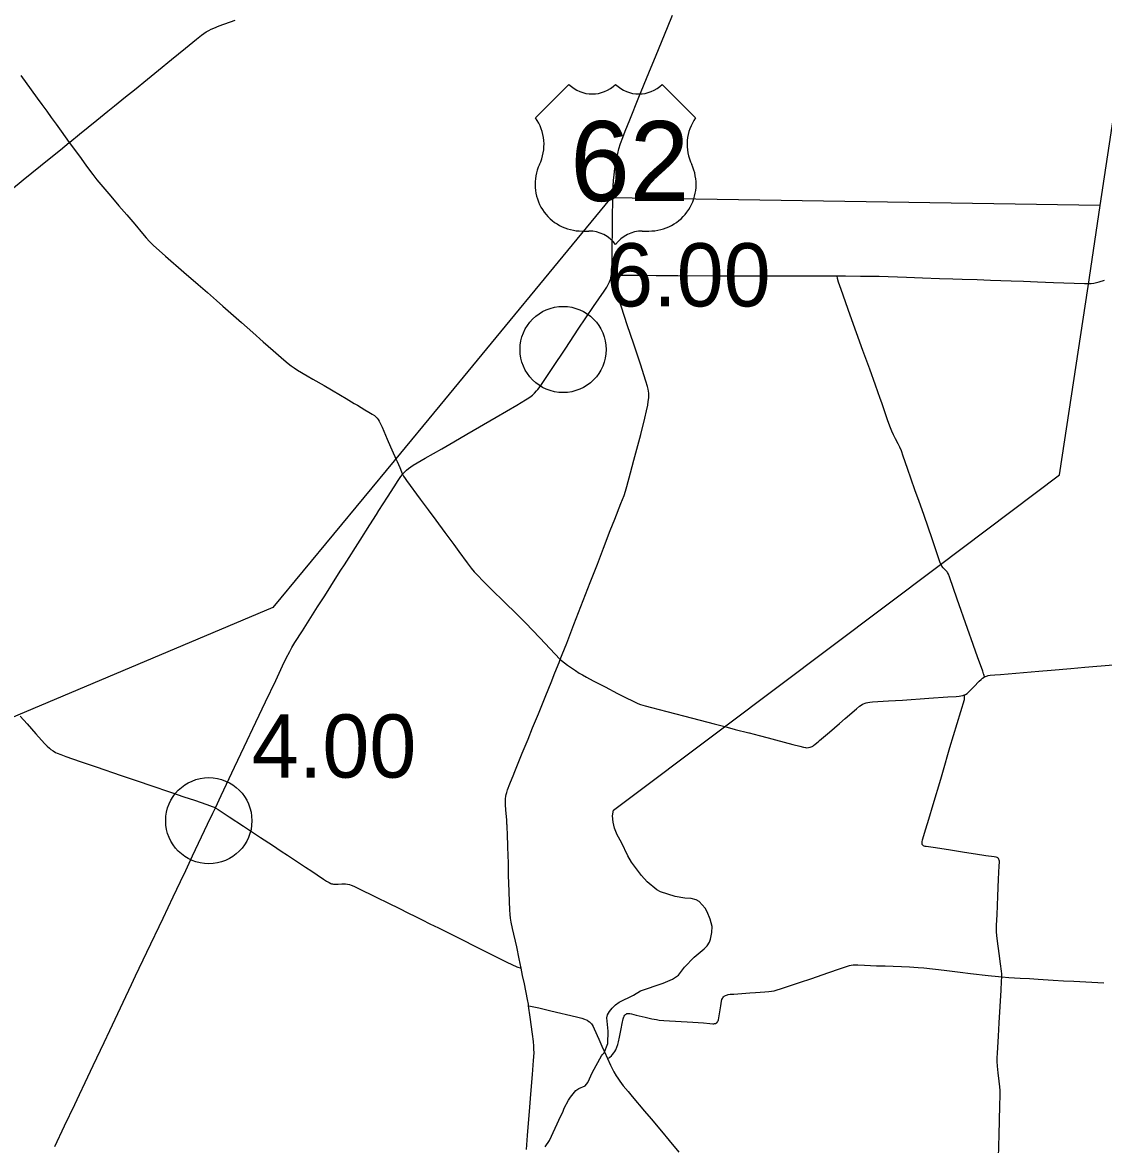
# Model space of a CAD drawing. Extents: x 1597222 to 1925846, y 496284 to 911751.
# Drawn here: x 1678855 to 1697673, y 517019 to 536551 of the extents above; entities that cross this region are included whole.
import ezdxf

# ---------------------------------------------------------------- set-up
doc = ezdxf.new("R2010")
doc.units = 0
for name, color, linetype in [('Default', 7, 'Continuous'), ('GM_X_County_Road', 7, 'Continuous'), ('GM_X_Township', 7, 'Continuous'), ('GM_X_Township_Road', 7, 'Continuous'), ('GM_X_US_Route', 7, 'Continuous'), ('GM_X_US_Shield', 7, 'Continuous')]:
    doc.layers.add(name, color=color, linetype=linetype)

msp = doc.modelspace()

# ---------------------------------------------------------------- linework, layer by layer
at = {"layer": 'Default'}
for centre in [(1688266, 530858), (1688266, 530858), (1682099, 522656), (1682099, 522656)]:
    msp.add_circle(centre, 750, dxfattribs=at)
at = {"layer": 'GM_X_County_Road'}
for points in [[(1679671, 534461), (1679681, 534469), (1679846, 534605), (1680152, 534852), (1680343, 535007), (1680458, 535099), (1680649, 535254), (1680803, 535378), (1681032, 535564), (1681222, 535719), (1681452, 535905), (1681693, 536102), (1681884, 536258), (1681973, 536330), (1682013, 536359), (1682054, 536387), (1682097, 536412), (1682141, 536434), (1682186, 536453), (1682278, 536489), (1682556, 536588)], [(1678825, 535628), (1679008, 535376), (1679114, 535230), (1679192, 535124), (1679279, 535005), (1679356, 534899), (1679442, 534779), (1679528, 534659), (1679671, 534461)], [(1678662, 533644), (1678866, 533809), (1679171, 534057), (1679376, 534222), (1679516, 534335), (1679671, 534461)], [(1679671, 534461), (1679691, 534432), (1679875, 534181), (1679973, 534049), (1680081, 533905), (1680152, 533814), (1680255, 533687), (1680393, 533524), (1680531, 533361), (1680670, 533200), (1680809, 533038), (1680946, 532875), (1681011, 532800), (1681067, 532740), (1681137, 532671), (1681234, 532582), (1681345, 532484), (1681667, 532204), (1681915, 531990), (1682076, 531850), (1682235, 531708), (1682346, 531611), (1682666, 531329), (1682863, 531156), (1683047, 530993), (1683219, 530840), (1683403, 530677), (1683479, 530614), (1683531, 530574), (1683585, 530536), (1683641, 530501), (1683811, 530402), (1683911, 530344), (1684109, 530229), (1684236, 530154), (1684391, 530062), (1684490, 530003), (1684631, 529920), (1684688, 529887), (1684814, 529810), (1684885, 529769), (1684941, 529735), (1684981, 529707), (1685005, 529687), (1685027, 529663), (1685046, 529637), (1685064, 529610), (1685087, 529566), (1685114, 529507), (1685205, 529297), (1685264, 529161), (1685311, 529057), (1685339, 528997), (1685357, 528956)], [(1688217, 525463), (1688251, 525549), (1688329, 525748), (1688453, 526069), (1688738, 526803), (1688864, 527124), (1688969, 527399), (1689088, 527705), (1689165, 527904), (1689273, 528179), (1689327, 528317), (1689354, 528394), (1689377, 528473), (1689441, 528711), (1689500, 528933), (1689618, 529376), (1689690, 529663), (1689720, 529791), (1689739, 529888), (1689749, 529953), (1689756, 530018), (1689760, 530053), (1689760, 530099), (1689755, 530134), (1689749, 530166), (1689737, 530214), (1689708, 530309), (1689611, 530605), (1689497, 530948), (1689384, 531290), (1689229, 531757), (1689137, 532026), (1689125, 532055), (1689106, 532081), (1689095, 532098)], [(1689107, 532152), (1689163, 532151), (1689393, 532150), (1689622, 532149), (1689885, 532147), (1690262, 532146), (1690885, 532143), (1691163, 532141), (1691426, 532140), (1691885, 532140), (1692409, 532139), (1693039, 532138)], [(1693039, 532138), (1693180, 532138), (1693442, 532136), (1693639, 532135), (1693770, 532133), (1694246, 532118), (1694524, 532107), (1694819, 532096), (1695048, 532090), (1695212, 532085), (1695474, 532075), (1695704, 532067), (1696064, 532053), (1696277, 532045), (1696523, 532035), (1696801, 532024), (1697162, 532010), (1697342, 532004), (1697407, 532004), (1697414, 532004)], [(1697414, 532004), (1697456, 532006), (1697505, 532012), (1697552, 532022), (1697599, 532035), (1697692, 532067)], [(1685357, 528956), (1685379, 528908), (1685425, 528802), (1685453, 528730), (1685466, 528698), (1685472, 528686)], [(1685472, 528686), (1685476, 528676), (1685490, 528652), (1685515, 528611), (1685542, 528575), (1685778, 528254), (1685915, 528070), (1686052, 527885), (1686207, 527673), (1686363, 527462), (1686450, 527343), (1686596, 527145), (1686666, 527053), (1686718, 526990), (1686763, 526942), (1686889, 526812), (1687005, 526697), (1687264, 526445), (1687439, 526273), (1687613, 526098), (1687863, 525838), (1688217, 525463)], [(1687415, 523482), (1687556, 523831), (1687656, 524074), (1687736, 524271), (1687835, 524514), (1687964, 524834), (1688056, 525062), (1688123, 525229), (1688196, 525412), (1688217, 525463)], [(1688217, 525463), (1688238, 525442), (1688345, 525366), (1688479, 525271), (1688548, 525226), (1688604, 525193), (1688676, 525153), (1688792, 525092), (1688997, 524989), (1689215, 524873), (1689331, 524813), (1689507, 524725), (1689567, 524698), (1689614, 524681), (1689692, 524655), (1689802, 524624), (1690072, 524554), (1690517, 524440), (1690898, 524340), (1691057, 524300), (1691082, 524293)], [(1695601, 525158), (1695621, 525168), (1695651, 525179), (1695667, 525182), (1695699, 525187), (1695781, 525195), (1695879, 525203), (1696549, 525260), (1696761, 525277), (1697104, 525307), (1697349, 525328), (1697839, 525371)], [(1695253, 524847), (1695269, 524854), (1695297, 524872), (1695322, 524893), (1695347, 524916), (1695415, 524987), (1695506, 525082), (1695541, 525116), (1695566, 525136), (1695593, 525154), (1695601, 525158)], [(1691506, 524183), (1691676, 524139), (1691834, 524098), (1691961, 524066), (1692262, 523985), (1692389, 523951), (1692453, 523934), (1692486, 523928), (1692502, 523927), (1692536, 523928), (1692568, 523935), (1692584, 523941), (1692599, 523948), (1692613, 523956), (1692627, 523966), (1692654, 523986), (1692704, 524029), (1692729, 524050), (1692904, 524199), (1693077, 524350), (1693176, 524436), (1693375, 524606), (1693426, 524648), (1693452, 524667), (1693480, 524684), (1693494, 524691), (1693524, 524703), (1693539, 524707), (1693571, 524715), (1693603, 524720), (1693652, 524724), (1693930, 524740), (1694175, 524756), (1694633, 524789), (1694961, 524811), (1695108, 524820), (1695157, 524824), (1695190, 524828), (1695222, 524836), (1695238, 524841), (1695253, 524847)], [(1678816, 524474), (1678936, 524340), (1679090, 524170), (1679242, 523998), (1679288, 523951), (1679324, 523918), (1679349, 523897), (1679389, 523870), (1679431, 523845), (1679461, 523831), (1679521, 523806), (1679613, 523772), (1679861, 523687), (1680141, 523593), (1680576, 523444), (1680871, 523344), (1681089, 523270), (1681430, 523155), (1681663, 523074), (1681849, 523012), (1682066, 522937), (1682159, 522903), (1682190, 522891), (1682213, 522880)], [(1691082, 524293), (1691263, 524245), (1691501, 524184), (1691506, 524183)], [(1687303, 522248), (1687298, 522381), (1687297, 522413), (1687293, 522544), (1687291, 522577), (1687289, 522593), (1687288, 522609), (1687284, 522674), (1687270, 522838), (1687263, 522936), (1687262, 522985), (1687265, 523034), (1687270, 523082), (1687276, 523114), (1687284, 523145), (1687300, 523192), (1687341, 523299), (1687408, 523466), (1687415, 523482)], [(1682213, 522880), (1682220, 522877), (1682262, 522851), (1682454, 522725), (1682701, 522562), (1683001, 522363), (1683207, 522228), (1683357, 522128), (1683467, 522056), (1683659, 521930), (1683782, 521849), (1683892, 521776), (1683987, 521712), (1684095, 521639), (1684150, 521602), (1684192, 521578), (1684221, 521564), (1684237, 521559), (1684252, 521556), (1684268, 521553), (1684300, 521551), (1684349, 521553), (1684415, 521557), (1684448, 521557), (1684481, 521556), (1684514, 521552), (1684546, 521544), (1684578, 521534), (1684624, 521516), (1684684, 521489), (1685022, 521322), (1685213, 521228), (1685419, 521126), (1685566, 521052), (1685698, 520987), (1685815, 520928), (1685948, 520863), (1686095, 520790), (1686388, 520644), (1686550, 520563), (1686697, 520490), (1687122, 520277), (1687284, 520196), (1687462, 520113), (1687535, 520089)], [(1687535, 520089), (1687502, 520252), (1687458, 520460), (1687385, 520780), (1687361, 520892), (1687349, 520957), (1687342, 521021), (1687336, 521103), (1687331, 521250), (1687321, 521578), (1687317, 521692), (1687317, 521791), (1687315, 521922), (1687311, 522053), (1687304, 522200), (1687303, 522248)], [(1689039, 518514), (1689067, 518528), (1689082, 518540), (1689106, 518562), (1689128, 518587), (1689148, 518613), (1689165, 518640), (1689181, 518669), (1689201, 518714), (1689218, 518760), (1689231, 518808), (1689249, 518888), (1689276, 519033), (1689296, 519129), (1689314, 519209), (1689324, 519241), (1689331, 519256), (1689340, 519269), (1689351, 519281), (1689364, 519291), (1689378, 519298), (1689394, 519302), (1689410, 519303), (1689427, 519301), (1689459, 519294), (1689538, 519274), (1689697, 519235), (1689809, 519210), (1689890, 519194), (1689938, 519187), (1690020, 519179), (1690527, 519149), (1690707, 519136), (1690822, 519126), (1690872, 519123), (1690888, 519123), (1690904, 519125), (1690920, 519129), (1690934, 519137), (1690946, 519146), (1690956, 519159), (1690963, 519174), (1690968, 519189), (1690975, 519222), (1691009, 519433), (1691023, 519514), (1691031, 519546), (1691038, 519561), (1691045, 519575), (1691055, 519588), (1691067, 519599), (1691080, 519609), (1691094, 519616), (1691110, 519622), (1691125, 519626), (1691142, 519630), (1691174, 519634), (1691240, 519639), (1691518, 519658), (1691616, 519666), (1691780, 519676), (1691845, 519681), (1691894, 519687), (1691942, 519697), (1691990, 519710), (1692052, 519729), (1692207, 519782), (1692378, 519839), (1692596, 519912), (1692876, 520007), (1693093, 520083), (1693201, 520120), (1693249, 520134), (1693281, 520141), (1693313, 520145), (1693346, 520147), (1693395, 520147), (1693510, 520142), (1693723, 520132), (1693870, 520127), (1694296, 520110), (1694444, 520102), (1694542, 520094), (1694901, 520055), (1695177, 520020), (1695357, 519999), (1695666, 519962), (1695846, 519943), (1695902, 519939)], [(1687664, 519436), (1687661, 519464), (1687647, 519545), (1687593, 519818), (1687562, 519963), (1687535, 520089)], [(1695902, 519939), (1696025, 519929), (1696222, 519917), (1696386, 519907), (1696533, 519898), (1696795, 519881), (1696975, 519871), (1697155, 519861), (1697679, 519836)], [(1687627, 516931), (1687647, 517176), (1687686, 517667), (1687703, 517896), (1687733, 518241), (1687753, 518480), (1687760, 518616), (1687759, 518681), (1687758, 518733), (1687751, 518812), (1687731, 518943), (1687690, 519236), (1687664, 519436)], [(1687664, 519436), (1687698, 519429), (1687842, 519396), (1688050, 519347), (1688497, 519243), (1688592, 519219), (1688640, 519204), (1688670, 519191), (1688685, 519184), (1688699, 519175), (1688726, 519154), (1688738, 519143), (1688749, 519131), (1688760, 519118), (1688770, 519104), (1688787, 519076), (1688808, 519031), (1688889, 518852), (1688942, 518732), (1688987, 518631)], [(1688987, 518631), (1689039, 518514)], [(1689039, 518514), (1689090, 518403), (1689126, 518329), (1689149, 518286), (1689190, 518216), (1689217, 518175), (1689254, 518121), (1689314, 518044), (1689396, 517942), (1689470, 517854), (1689682, 517603), (1689798, 517465), (1689976, 517251), (1690113, 517088), (1690281, 516886)]]:
    msp.add_lwpolyline(points, dxfattribs=at)
at = {"layer": 'GM_X_Township'}
for points in [[(1687952, 516977), (1688030, 517088), (1688224, 517518), (1688259, 517580), (1688284, 517652), (1688361, 517791), (1688394, 517843), (1688490, 517960), (1688540, 517993), (1688651, 518042), (1688698, 518100), (1688778, 518279), (1688934, 518563), (1688947, 518578), (1688979, 518615), (1689047, 518780), (1689048, 518991), (1689027, 519224), (1689041, 519279), (1689074, 519337), (1689119, 519393), (1689180, 519452), (1689242, 519497), (1689494, 519622), (1689616, 519693), (1690006, 519830), (1690169, 519896), (1690272, 519969), (1690380, 520106), (1690549, 520280), (1690719, 520425), (1690774, 520480), (1690812, 520542), (1690831, 520596), (1690853, 520709), (1690858, 520816), (1690825, 520942), (1690771, 521071), (1690736, 521132), (1690635, 521247), (1690583, 521280), (1690497, 521301), (1690387, 521308), (1690215, 521337), (1689960, 521418), (1689896, 521451), (1689729, 521593), (1689632, 521701), (1689459, 521933), (1689392, 522044), (1689281, 522278), (1689208, 522409), (1689162, 522526), (1689137, 522633), (1689124, 522743), (1689142, 522837), (1691050, 524271), (1694788, 527081), (1696909, 528675), (1697404, 531952), (1697617, 533364), (1698092, 536511)], [(1697617, 533364), (1689097, 533498), (1689075, 533471), (1686122, 529882), (1685324, 528919), (1683211, 526366), (1678773, 524491), (1673121, 522104), (1670207, 520873), (1664451, 518441), (1661353, 517132), (1661136, 517041)]]:
    msp.add_lwpolyline(points, dxfattribs=at)
at = {"layer": 'GM_X_Township_Road'}
for points in [[(1694842, 527119), (1694832, 527143), (1694779, 527299), (1694686, 527579), (1694626, 527750), (1694545, 527984), (1694461, 528213), (1694391, 528414), (1694262, 528786), (1694188, 529003), (1694154, 529096), (1694129, 529156), (1694101, 529216), (1694054, 529302), (1694016, 529375), (1693989, 529434), (1693952, 529526), (1693912, 529633), (1693870, 529758), (1693813, 529929), (1693786, 530006), (1693704, 530238), (1693603, 530515), (1693486, 530840), (1693265, 531457), (1693104, 531905), (1693062, 532029), (1693044, 532094), (1693039, 532138)], [(1695409, 525707), (1695403, 525723), (1695304, 526001), (1695124, 526512), (1694989, 526899), (1694972, 526945), (1694958, 526975), (1694949, 526988), (1694939, 527001), (1694928, 527014), (1694881, 527059), (1694860, 527084), (1694844, 527113), (1694842, 527119)], [(1695601, 525158), (1695589, 525198), (1695584, 525213), (1695569, 525260), (1695480, 525507), (1695409, 525707)], [(1695902, 519939), (1695903, 519955), (1695901, 519988), (1695897, 520037), (1695880, 520167), (1695856, 520346), (1695827, 520558), (1695815, 520655), (1695811, 520721), (1695810, 520770), (1695811, 520836), (1695819, 521016), (1695834, 521344), (1695845, 521639), (1695857, 521869), (1695860, 521935), (1695860, 521951), (1695857, 521967), (1695853, 521983), (1695845, 521997), (1695833, 522008), (1695819, 522016), (1695803, 522021), (1695771, 522027), (1695624, 522047), (1695446, 522075), (1695251, 522105), (1695008, 522142), (1694748, 522182), (1694586, 522206), (1694569, 522209), (1694553, 522214), (1694539, 522221), (1694527, 522231), (1694518, 522244), (1694513, 522259), (1694513, 522275), (1694514, 522291), (1694522, 522324), (1694580, 522512), (1694631, 522685), (1694706, 522937), (1694839, 523377), (1694876, 523503), (1695000, 523928), (1695252, 524765), (1695255, 524790), (1695254, 524823), (1695253, 524847)], [(1695842, 516793), (1695856, 517187), (1695869, 517695), (1695873, 517876), (1695872, 517958), (1695868, 518023), (1695857, 518121), (1695839, 518268), (1695829, 518382), (1695824, 518464), (1695824, 518530), (1695826, 518612), (1695844, 518907), (1695856, 519136), (1695891, 519709), (1695899, 519857), (1695902, 519939)]]:
    msp.add_lwpolyline(points, dxfattribs=at)
at = {"layer": 'GM_X_US_Route'}
msp.add_lwpolyline([(1679422, 516988), (1679590, 517344), (1679765, 517715), (1679849, 517893), (1679948, 518101), (1680088, 518397), (1680278, 518798), (1680375, 519006), (1680608, 519495), (1680755, 519806), (1680825, 519955), (1681022, 520370), (1681304, 520962), (1681481, 521332), (1681607, 521599), (1681698, 521792), (1681817, 522044), (1682077, 522593), (1682168, 522785), (1682213, 522880), (1682316, 523097), (1682456, 523393), (1682548, 523586), (1682717, 523942), (1682920, 524372), (1683088, 524728), (1683265, 525098), (1683383, 525350), (1683447, 525483), (1683507, 525600), (1683547, 525672), (1683598, 525756), (1683729, 525963), (1683993, 526379), (1684116, 526573), (1684327, 526905), (1684399, 527015), (1684462, 527111), (1684734, 527541), (1684902, 527804), (1685016, 527984), (1685060, 528053), (1685209, 528288), (1685323, 528469), (1685394, 528579), (1685441, 528646), (1685471, 528685), (1685472, 528686), (1685503, 528721), (1685538, 528755), (1685576, 528786), (1685616, 528815), (1685656, 528842), (1685726, 528885), (1685868, 528966), (1686153, 529130), (1686366, 529253), (1686593, 529385), (1687103, 529682), (1687458, 529888), (1687614, 529980), (1687669, 530015), (1687709, 530045), (1687735, 530065), (1687771, 530099), (1687804, 530136), (1687825, 530161), (1687864, 530214), (1688074, 530528), (1688312, 530882), (1688531, 531209), (1688796, 531605), (1688980, 531876), (1689025, 531945), (1689049, 531988), (1689071, 532033), (1689089, 532079), (1689095, 532098), (1689099, 532111), (1689106, 532143), (1689107, 532152), (1689110, 532176), (1689114, 532225), (1689118, 532357), (1689118, 532472), (1689119, 532652), (1689123, 532931), (1689126, 533128), (1689133, 533496), (1689134, 533554), (1689138, 533702), (1689144, 533800), (1689153, 533898), (1689168, 534011), (1689183, 534108), (1689199, 534189), (1689217, 534269), (1689238, 534348), (1689267, 534441), (1689305, 534550), (1689345, 534657), (1689425, 534855), (1689586, 535250), (1689760, 535675), (1689884, 535979), (1690083, 536464), (1690171, 536677)], dxfattribs=at)
at = {"layer": 'GM_X_US_Shield'}
for p, q in [((1688367, 535472), (1687787, 534892)), ((1690572, 534892), (1689992, 535472)), ((1688599, 532920), (1688715, 532920)), ((1689644, 532920), (1689760, 532920))]:
    msp.add_line(p, q, dxfattribs=at)
for centre, radius, start, end in [((1688773, 535886), 580, 225.573, 314.427), ((1689585, 535886), 580, 225.573, 314.427), ((1687122, 534426), 812, 334.5471, 35.0009), ((1691237, 534426), 812, 144.9991, 205.4529), ((1688590, 533732), 812, 154.8319, 270.6383), ((1689769, 533732), 812, 269.3617, 25.1681), ((1688715, 532340), 580, 36.8699, 90), ((1689644, 532340), 580, 90, 143.1301)]:
    msp.add_arc(centre, radius, start, end, dxfattribs=at)

# ---------------------------------------------------------------- texts
at = {"layer": 'Default'}
for s, p in [('6.00', (1689016, 531608)), ('6.00', (1689016, 531608)), ('4.00', (1682849, 523406)), ('4.00', (1682849, 523406))]:
    msp.add_text(s, height=1100, dxfattribs=at).set_placement(p)
at = {"layer": 'GM_X_US_Shield'}
msp.add_text('62', height=1392.2, dxfattribs=at).set_placement((1688391, 533442))

doc.saveas('drawing.dxf')
